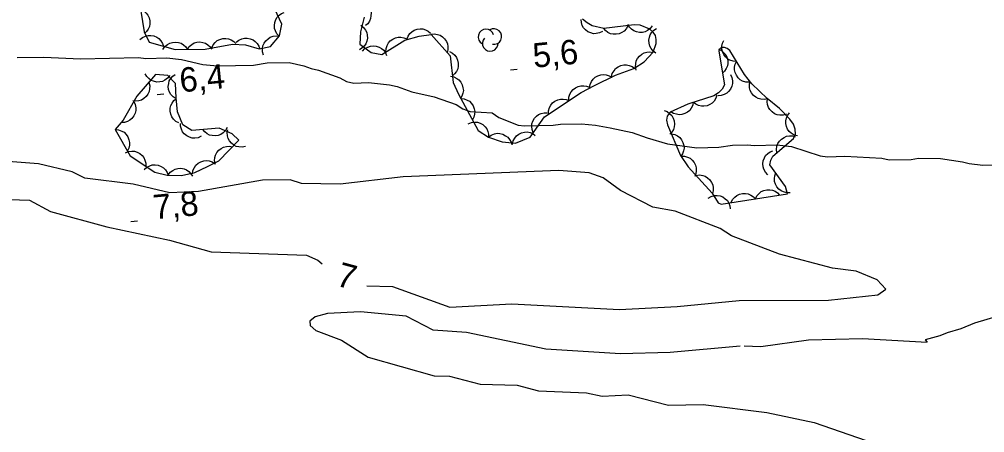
# Model space of a CAD drawing. Extents: x 336540 to 340074, y 5572036 to 5573747.
# Drawn here: x 336901.8 to 337020.3, y 5572687.6 to 5572738.3 of the extents above; entities that cross this region are included whole.
import ezdxf

# ---------------------------------------------------------------- set-up
doc = ezdxf.new("R2010")
doc.units = 0
for name, color, linetype in [('Niveau 2', 7, 'Continuous'), ('Niveau 3', 7, 'Continuous'), ('Niveau 44', 7, 'Continuous')]:
    doc.layers.add(name, color=color, linetype=linetype)

msp = doc.modelspace()

# ---------------------------------------------------------------- linework, layer by layer
at = {"layer": 'Niveau 2'}
for points in [[(336901.55, 5572733.62), (336904.82, 5572733.69), (336909.33, 5572733.46), (336916.43, 5572733.62), (336917.33, 5572733.53), (336919.92, 5572733.59), (336921.73, 5572733.4), (336924.34, 5572732.79), (336926.14, 5572732.6), (336930.54, 5572732.7), (336932.22, 5572732.97), (336934.93, 5572733.03), (336936.74, 5572732.62), (336937.65, 5572732.3), (336938.55, 5572732.1), (336941.17, 5572731.14), (336941.97, 5572730.71), (336942.87, 5572730.5), (336944.67, 5572730.55), (336947.27, 5572730.27), (336948.18, 5572730.06), (336950, 5572729.43), (336952.72, 5572728.81), (336955.44, 5572727.86), (336956.24, 5572727.32), (336957.15, 5572727), (336959.86, 5572726.83), (336960.66, 5572726.29), (336963.05, 5572725.33), (336963.84, 5572725.23), (336967.33, 5572725.31), (336968.23, 5572725.45), (336970.82, 5572725.51), (336972.52, 5572725.32), (336974.33, 5572725.02), (336977.05, 5572724.41), (336978.87, 5572723.77), (336981.36, 5572723.04)], [(336981.36, 5572723.04), (336984.08, 5572722.65), (336984.98, 5572722.56), (336987.68, 5572722.62), (336989.37, 5572722.89), (336991.17, 5572722.93), (336992.07, 5572722.84), (336994.78, 5572722.9), (336996.58, 5572722.71), (337000.11, 5572721.55), (337001.01, 5572721.46), (337003.15, 5572721.51), (337007.66, 5572721.28), (337008.57, 5572721.07), (337011.27, 5572721.13), (337012.17, 5572721.27), (337014.88, 5572721.22), (337017.59, 5572720.83), (337018.38, 5572720.62), (337020.08, 5572720.43), (337025.26, 5572720.55)], [(336944.47, 5572705.62), (336947.61, 5572705.51), (336954.67, 5572702.99), (336962.26, 5572703.38), (336975.49, 5572702.69), (336982.58, 5572703.05), (336990.15, 5572703.78), (337001.15, 5572703.84), (337007.2, 5572704.5), (337008.18, 5572705.21), (337007.1, 5572706.35), (337004.52, 5572707.41), (337001.62, 5572707.76), (336995.11, 5572709.47), (336989.24, 5572711.72), (336987.84, 5572712.65), (336982.32, 5572714.76), (336979.57, 5572715.27), (336975.59, 5572717.29), (336973.48, 5572718.87), (336971.75, 5572719.46), (336968.02, 5572719.77), (336948.94, 5572718.98), (336941.2, 5572718.07), (336936.46, 5572718.15), (336935.08, 5572718.61), (336931.68, 5572718.59), (336923.81, 5572717.17), (336920.28, 5572717), (336915.81, 5572718.1), (336909.86, 5572718.83), (336908.3, 5572719.58), (336904.18, 5572720.57), (336897.73, 5572721.07)], [(336899.33, 5572716.24), (336903.06, 5572716.11), (336905.65, 5572714.72), (336912.54, 5572712.86), (336920.24, 5572711.22), (336925.38, 5572709.78), (336937.08, 5572709.38), (336938.47, 5572708.76), (336938.98, 5572708.29)], [(336990.28, 5572698.2), (336981.69, 5572697.42), (336975.6, 5572697.27), (336966.44, 5572697.82), (336956.69, 5572699.85), (336952.6, 5572700.17), (336949.31, 5572701.88), (336943.68, 5572702.42), (336939.64, 5572702.22), (336938.14, 5572701.8), (336937.49, 5572701.26), (336937.51, 5572700.74), (336938.23, 5572700.12), (336941.35, 5572698.91), (336944.65, 5572696.86), (336952.73, 5572694.56), (336954.61, 5572694.5), (336958.36, 5572693.51), (336962.94, 5572693.4), (336965.53, 5572692.69), (336971.45, 5572692.46), (336973.34, 5572692.07), (336976.53, 5572692.23), (336981.51, 5572690.96), (336985.74, 5572691.01), (336993.58, 5572690.05), (336999.39, 5572688.81), (337005.75, 5572686.62)], [(337023.2, 5572702.25), (337019.05, 5572701.02)], [(337019.05, 5572701.02), (337017.38, 5572700.31), (337015.7, 5572699.82), (337014.81, 5572699.46), (337013.01, 5572698.97), (337013.25, 5572698.69)], [(336990.79, 5572698.23), (336992.81, 5572698.14), (336998.68, 5572698.98), (337005.29, 5572699.14), (337013.25, 5572698.69)]]:
    msp.add_lwpolyline(points, dxfattribs=at)
at = {"layer": 'Niveau 3'}
for p, q in [((336962.11, 5572732.13), (336962.91, 5572732.21)), ((336918.75, 5572729.11), (336919.55, 5572729.19)), ((336915.51, 5572713.52), (336916.31, 5572713.6))]:
    msp.add_line(p, q, dxfattribs=at)
at = {"layer": 'Niveau 44'}
for points in [[(336916.38, 5572741.65), (336917.14, 5572736.8), (336917.75, 5572735.52), (336920.94, 5572734.63), (336924.63, 5572734.66), (336927.99, 5572735.27), (336929.56, 5572735.19), (336931.25, 5572734.71), (336932.63, 5572734.97), (336933.74, 5572736.32), (336934.04, 5572737.75), (336932.63, 5572740.76)], [(336943.87, 5572740.51), (336944.25, 5572740.33), (336944.55, 5572740.06), (336944.76, 5572739.8), (336944.9, 5572739.48), (336944.99, 5572739.12), (336944.98, 5572738.74), (336944.94, 5572738.42), (336944.79, 5572738.1), (336944.58, 5572737.79), (336944.32, 5572737.55)], [(336916.71, 5572739.53), (336917.09, 5572739.36), (336917.39, 5572739.08), (336917.61, 5572738.83), (336917.75, 5572738.51), (336917.84, 5572738.15), (336917.83, 5572737.77), (336917.79, 5572737.44), (336917.65, 5572737.12), (336917.44, 5572736.82), (336917.18, 5572736.57)], [(336933.72, 5572736.24), (336933.43, 5572736.54), (336933.25, 5572736.9), (336933.14, 5572737.21), (336933.12, 5572737.56), (336933.16, 5572737.93), (336933.3, 5572738.29), (336933.45, 5572738.58), (336933.7, 5572738.82), (336934.01, 5572739.04), (336934.34, 5572739.17)], [(336943.72, 5572737.6), (336944.06, 5572737.34), (336944.29, 5572737.01), (336944.45, 5572736.72), (336944.52, 5572736.38), (336944.54, 5572736.01), (336944.45, 5572735.64), (336944.35, 5572735.33), (336944.14, 5572735.04), (336943.87, 5572734.79), (336943.56, 5572734.6)], [(336944.16, 5572738.6), (336943.68, 5572736.8), (336943.6, 5572735.28), (336944.99, 5572734.24), (336946.31, 5572734), (336949.12, 5572735.77), (336950.91, 5572736.26), (336952.35, 5572736.47), (336954.68, 5572733.85), (336955.08, 5572730.55), (336955.72, 5572729.12), (336958.15, 5572724.69), (336959.42, 5572723.85), (336961.09, 5572723.3), (336962.71, 5572723.13), (336964.52, 5572723.84), (336966.27, 5572726.37), (336970.79, 5572729.33), (336972.41, 5572730.21), (336975, 5572731.45), (336977.24, 5572732.3), (336978.51, 5572733.12), (336979.61, 5572734.3), (336979.98, 5572735.35), (336979.99, 5572735.86), (336979.91, 5572736.35), (336979.63, 5572736.75), (336979.2, 5572737.11), (336978.02, 5572737.6), (336977.3, 5572737.64), (336973.56, 5572737.22), (336972.14, 5572737.53), (336971.51, 5572737.88), (336970.94, 5572738.35)], [(336973.39, 5572736.83), (336973.02, 5572736.65), (336972.62, 5572736.58), (336972.29, 5572736.56), (336971.95, 5572736.65), (336971.61, 5572736.8), (336971.31, 5572737.04), (336971.08, 5572737.27), (336970.92, 5572737.58), (336970.8, 5572737.93), (336970.77, 5572738.29)], [(336979.51, 5572737.52), (336979.26, 5572737.18), (336978.93, 5572736.95), (336978.64, 5572736.79), (336978.29, 5572736.72), (336977.92, 5572736.71), (336977.55, 5572736.79), (336977.24, 5572736.9), (336976.96, 5572737.11), (336976.7, 5572737.37), (336976.52, 5572737.68)], [(336949.39, 5572735.84), (336949.53, 5572736.24), (336949.76, 5572736.57), (336949.99, 5572736.81), (336950.29, 5572736.99), (336950.64, 5572737.12), (336951.02, 5572737.15), (336951.35, 5572737.15), (336951.68, 5572737.04), (336952.01, 5572736.87), (336952.29, 5572736.64)], [(336952.33, 5572736.49), (336952.75, 5572736.55), (336953.15, 5572736.48), (336953.46, 5572736.38), (336953.76, 5572736.19), (336954.02, 5572735.94), (336954.23, 5572735.61), (336954.37, 5572735.32), (336954.42, 5572734.97), (336954.41, 5572734.6), (336954.32, 5572734.25)], [(336976.52, 5572737.55), (336976.33, 5572737.18), (336976.04, 5572736.89), (336975.78, 5572736.69), (336975.45, 5572736.56), (336975.09, 5572736.49), (336974.71, 5572736.51), (336974.38, 5572736.56), (336974.07, 5572736.72), (336973.77, 5572736.94), (336973.54, 5572737.22)], [(336979.96, 5572734.19), (336979.62, 5572734.43), (336979.37, 5572734.75), (336979.2, 5572735.04), (336979.12, 5572735.38), (336979.09, 5572735.75), (336979.16, 5572736.12), (336979.26, 5572736.44), (336979.46, 5572736.73), (336979.71, 5572736.99), (336980.02, 5572737.19)], [(336916.61, 5572735.84), (336916.93, 5572736.11), (336917.3, 5572736.27), (336917.62, 5572736.36), (336917.97, 5572736.36), (336918.33, 5572736.29), (336918.68, 5572736.12), (336918.96, 5572735.96), (336919.19, 5572735.69), (336919.38, 5572735.37), (336919.5, 5572735.03)], [(336919.44, 5572734.62), (336919.67, 5572734.97), (336919.99, 5572735.22), (336920.27, 5572735.4), (336920.61, 5572735.49), (336920.98, 5572735.53), (336921.35, 5572735.47), (336921.67, 5572735.38), (336921.96, 5572735.19), (336922.24, 5572734.94), (336922.44, 5572734.64)], [(336922.44, 5572734.64), (336922.67, 5572734.99), (336922.99, 5572735.25), (336923.27, 5572735.42), (336923.61, 5572735.52), (336923.98, 5572735.55), (336924.35, 5572735.49), (336924.67, 5572735.4), (336924.96, 5572735.21), (336925.24, 5572734.96), (336925.44, 5572734.67)], [(336925.43, 5572734.81), (336925.6, 5572735.19), (336925.86, 5572735.5), (336926.11, 5572735.72), (336926.43, 5572735.86), (336926.78, 5572735.96), (336927.17, 5572735.97), (336927.49, 5572735.94), (336927.82, 5572735.8), (336928.13, 5572735.6), (336928.38, 5572735.34)], [(336928.43, 5572735.51), (336928.75, 5572735.78), (336929.12, 5572735.94), (336929.44, 5572736.03), (336929.79, 5572736.02), (336930.16, 5572735.95), (336930.5, 5572735.79), (336930.78, 5572735.62), (336931.01, 5572735.35), (336931.2, 5572735.03), (336931.32, 5572734.69)], [(336931.78, 5572733.94), (336931.66, 5572734.34), (336931.67, 5572734.75), (336931.71, 5572735.07), (336931.86, 5572735.39), (336932.07, 5572735.7), (336932.36, 5572735.95), (336932.62, 5572736.14), (336932.96, 5572736.24), (336933.33, 5572736.29), (336933.69, 5572736.26)], [(336946.82, 5572734.32), (336946.83, 5572734.74), (336946.97, 5572735.12), (336947.11, 5572735.42), (336947.35, 5572735.68), (336947.65, 5572735.9), (336948, 5572736.05), (336948.31, 5572736.14), (336948.66, 5572736.13), (336949.03, 5572736.07), (336949.36, 5572735.92)], [(336989.84, 5572733.16), (336989.42, 5572733.18), (336989.04, 5572733.32), (336988.75, 5572733.47), (336988.49, 5572733.72), (336988.27, 5572734.01), (336988.13, 5572734.37), (336988.05, 5572734.68), (336988.06, 5572735.04), (336988.13, 5572735.4), (336988.28, 5572735.73)], [(336943.95, 5572734.43), (336944.24, 5572734.73), (336944.6, 5572734.92), (336944.91, 5572735.04), (336945.26, 5572735.07), (336945.63, 5572735.03), (336945.99, 5572734.9), (336946.28, 5572734.76), (336946.54, 5572734.52), (336946.76, 5572734.22), (336946.9, 5572733.89)], [(336954.62, 5572734.38), (336954.99, 5572734.19), (336955.28, 5572733.91), (336955.48, 5572733.65), (336955.61, 5572733.32), (336955.69, 5572732.96), (336955.67, 5572732.58), (336955.62, 5572732.25), (336955.47, 5572731.94), (336955.25, 5572731.64), (336954.98, 5572731.4)], [(336977.53, 5572732.07), (336977.44, 5572732.48), (336977.47, 5572732.88), (336977.53, 5572733.21), (336977.7, 5572733.52), (336977.93, 5572733.81), (336978.23, 5572734.04), (336978.51, 5572734.21), (336978.85, 5572734.29), (336979.22, 5572734.32), (336979.58, 5572734.27)], [(336996.12, 5572716.89), (336995.86, 5572717.81), (336993.94, 5572720.45), (336994.06, 5572721.03), (336994.32, 5572721.53), (336996.83, 5572723.71), (336997.07, 5572724.22), (336997.03, 5572724.82), (336996.82, 5572725.44), (336996.37, 5572726.08), (336995.1, 5572727.37), (336993.6, 5572728.61), (336991.73, 5572730.41), (336990.81, 5572731.56), (336989.04, 5572734.48), (336988.69, 5572734.75), (336988.38, 5572734.87), (336988.05, 5572734.85), (336987.79, 5572734.7), (336987.66, 5572734.41), (336988.37, 5572730.28), (336988.07, 5572729.75), (336987.64, 5572729.28), (336987.07, 5572728.92), (336983.87, 5572727.9), (336981.72, 5572726.93), (336981.33, 5572726.44), (336981.25, 5572725.93), (336981.39, 5572725.36), (336982.97, 5572721.62), (336983.91, 5572720.23), (336986.85, 5572716.96), (336987.61, 5572715.78), (336987.94, 5572715.62), (336996.12, 5572716.89)], [(336987.62, 5572734.67), (336988, 5572734.5), (336988.3, 5572734.23), (336988.52, 5572733.98), (336988.67, 5572733.66), (336988.76, 5572733.31), (336988.76, 5572732.92), (336988.73, 5572732.6), (336988.59, 5572732.27), (336988.38, 5572731.96), (336988.12, 5572731.71)], [(336991.39, 5572730.6), (336990.98, 5572730.62), (336990.59, 5572730.75), (336990.3, 5572730.91), (336990.05, 5572731.15), (336989.83, 5572731.45), (336989.69, 5572731.8), (336989.6, 5572732.12), (336989.61, 5572732.47), (336989.69, 5572732.83), (336989.84, 5572733.16)], [(336974.51, 5572731.26), (336974.6, 5572731.67), (336974.81, 5572732.02), (336975.01, 5572732.28), (336975.3, 5572732.49), (336975.63, 5572732.65), (336976.01, 5572732.72), (336976.33, 5572732.75), (336976.67, 5572732.67), (336977.02, 5572732.53), (336977.31, 5572732.33)], [(336913.59, 5572724.79), (336915.44, 5572721.55), (336918.46, 5572719.57), (336919.96, 5572719.21), (336921.71, 5572719.13), (336923.34, 5572719.5), (336924.93, 5572720.24), (336926.31, 5572720.97), (336928.75, 5572723.49), (336927.93, 5572724.26), (336926.33, 5572724.96), (336923, 5572724.67), (336921.9, 5572725.36), (336921.24, 5572726.97), (336921.05, 5572728.68), (336920.98, 5572730.44), (336920.03, 5572731.44), (336918.54, 5572731.54), (336916.23, 5572728.89), (336914.55, 5572725.96), (336913.59, 5572724.79)], [(336917.71, 5572730.59), (336917.82, 5572730.18), (336917.8, 5572729.78), (336917.75, 5572729.45), (336917.59, 5572729.14), (336917.37, 5572728.84), (336917.08, 5572728.6), (336916.8, 5572728.42), (336916.47, 5572728.32), (336916.1, 5572728.28), (336915.74, 5572728.33)], [(336920.27, 5572731.42), (336920.02, 5572731.09), (336919.68, 5572730.86), (336919.39, 5572730.71), (336919.05, 5572730.64), (336918.68, 5572730.63), (336918.3, 5572730.72), (336918, 5572730.83), (336917.72, 5572731.04), (336917.46, 5572731.31), (336917.28, 5572731.62)], [(336921.05, 5572728.58), (336920.7, 5572728.8), (336920.43, 5572729.1), (336920.25, 5572729.38), (336920.14, 5572729.71), (336920.1, 5572730.08), (336920.15, 5572730.46), (336920.22, 5572730.78), (336920.4, 5572731.08), (336920.65, 5572731.36), (336920.93, 5572731.57)], [(336954.73, 5572731.33), (336955.14, 5572731.26), (336955.5, 5572731.08), (336955.78, 5572730.89), (336956, 5572730.62), (336956.18, 5572730.29), (336956.27, 5572729.92), (336956.32, 5572729.6), (336956.26, 5572729.25), (336956.14, 5572728.9), (336955.95, 5572728.6)], [(336971.82, 5572729.93), (336971.88, 5572730.34), (336972.06, 5572730.71), (336972.24, 5572730.98), (336972.5, 5572731.21), (336972.82, 5572731.4), (336973.19, 5572731.51), (336973.51, 5572731.56), (336973.86, 5572731.51), (336974.21, 5572731.4), (336974.53, 5572731.22)], [(336989.09, 5572731.55), (336989.27, 5572731.17), (336989.34, 5572730.77), (336989.35, 5572730.44), (336989.26, 5572730.1), (336989.11, 5572729.77), (336988.87, 5572729.47), (336988.64, 5572729.24), (336988.32, 5572729.08), (336987.97, 5572728.96), (336987.61, 5572728.94)], [(336993.64, 5572728.57), (336993.23, 5572728.48), (336992.83, 5572728.52), (336992.51, 5572728.59), (336992.2, 5572728.76), (336991.91, 5572728.99), (336991.68, 5572729.3), (336991.52, 5572729.58), (336991.44, 5572729.92), (336991.42, 5572730.29), (336991.48, 5572730.65)], [(336969.27, 5572728.34), (336969.28, 5572728.76), (336969.4, 5572729.14), (336969.55, 5572729.44), (336969.78, 5572729.7), (336970.07, 5572729.93), (336970.42, 5572730.08), (336970.73, 5572730.18), (336971.09, 5572730.18), (336971.45, 5572730.12), (336971.78, 5572729.98)], [(336915.86, 5572728.24), (336916.04, 5572727.87), (336916.11, 5572727.47), (336916.12, 5572727.14), (336916.03, 5572726.8), (336915.87, 5572726.46), (336915.63, 5572726.16), (336915.39, 5572725.94), (336915.08, 5572725.78), (336914.73, 5572725.67), (336914.37, 5572725.64)], [(336921.39, 5572725.6), (336921.02, 5572725.79), (336920.73, 5572726.08), (336920.53, 5572726.34), (336920.4, 5572726.66), (336920.33, 5572727.03), (336920.35, 5572727.41), (336920.41, 5572727.73), (336920.57, 5572728.05), (336920.79, 5572728.34), (336921.06, 5572728.58)], [(336956, 5572728.62), (336956.41, 5572728.58), (336956.79, 5572728.42), (336957.08, 5572728.26), (336957.32, 5572728), (336957.52, 5572727.7), (336957.65, 5572727.33), (336957.72, 5572727.02), (336957.69, 5572726.67), (336957.6, 5572726.31), (336957.44, 5572725.99)], [(336966.76, 5572726.69), (336966.77, 5572727.11), (336966.9, 5572727.5), (336967.04, 5572727.8), (336967.27, 5572728.06), (336967.56, 5572728.29), (336967.91, 5572728.44), (336968.22, 5572728.54), (336968.58, 5572728.54), (336968.94, 5572728.48), (336969.27, 5572728.34)], [(336984.54, 5572728.2), (336984.47, 5572727.79), (336984.29, 5572727.43), (336984.1, 5572727.15), (336983.83, 5572726.93), (336983.5, 5572726.75), (336983.13, 5572726.65), (336982.81, 5572726.61), (336982.46, 5572726.66), (336982.11, 5572726.78), (336981.8, 5572726.97)], [(336987.43, 5572729.03), (336987.31, 5572728.63), (336987.09, 5572728.29), (336986.87, 5572728.04), (336986.57, 5572727.86), (336986.23, 5572727.71), (336985.85, 5572727.66), (336985.53, 5572727.65), (336985.19, 5572727.74), (336984.85, 5572727.9), (336984.57, 5572728.12)], [(336995.96, 5572726.66), (336995.56, 5572726.54), (336995.15, 5572726.55), (336994.82, 5572726.59), (336994.5, 5572726.74), (336994.2, 5572726.95), (336993.95, 5572727.24), (336993.76, 5572727.51), (336993.66, 5572727.85), (336993.61, 5572728.21), (336993.65, 5572728.57)], [(336980.96, 5572727.13), (336981.35, 5572726.99), (336981.67, 5572726.74), (336981.91, 5572726.51), (336982.07, 5572726.2), (336982.19, 5572725.85), (336982.22, 5572725.47), (336982.21, 5572725.14), (336982.09, 5572724.81), (336981.91, 5572724.48), (336981.67, 5572724.22)], [(336964.9, 5572724.39), (336964.75, 5572724.78), (336964.72, 5572725.18), (336964.74, 5572725.51), (336964.86, 5572725.84), (336965.04, 5572726.17), (336965.31, 5572726.44), (336965.56, 5572726.65), (336965.88, 5572726.78), (336966.25, 5572726.86), (336966.61, 5572726.86)], [(336997.31, 5572724), (336996.9, 5572724.11), (336996.56, 5572724.33), (336996.31, 5572724.54), (336996.11, 5572724.83), (336995.97, 5572725.17), (336995.9, 5572725.55), (336995.89, 5572725.88), (336995.98, 5572726.22), (336996.13, 5572726.55), (336996.35, 5572726.84)], [(336913.59, 5572724.79), (336914.01, 5572724.76), (336914.39, 5572724.61), (336914.67, 5572724.45), (336914.92, 5572724.2), (336915.13, 5572723.9), (336915.26, 5572723.54), (336915.34, 5572723.22), (336915.32, 5572722.87), (336915.24, 5572722.51), (336915.08, 5572722.18)], [(336924.14, 5572723.96), (336923.76, 5572723.79), (336923.35, 5572723.74), (336923.02, 5572723.74), (336922.69, 5572723.85), (336922.36, 5572724.01), (336922.07, 5572724.27), (336921.85, 5572724.51), (336921.71, 5572724.83), (336921.61, 5572725.19), (336921.6, 5572725.55)], [(336927.33, 5572725.05), (336927.13, 5572724.68), (336926.83, 5572724.4), (336926.57, 5572724.2), (336926.24, 5572724.08), (336925.87, 5572724.02), (336925.49, 5572724.05), (336925.17, 5572724.11), (336924.86, 5572724.28), (336924.57, 5572724.51), (336924.34, 5572724.79)], [(336929.57, 5572722.72), (336929.17, 5572722.62), (336928.76, 5572722.65), (336928.44, 5572722.72), (336928.13, 5572722.89), (336927.84, 5572723.12), (336927.61, 5572723.42), (336927.44, 5572723.7), (336927.36, 5572724.04), (336927.33, 5572724.41), (336927.39, 5572724.77)], [(336956.92, 5572725.51), (336957.3, 5572725.66), (336957.71, 5572725.7), (336958.04, 5572725.69), (336958.37, 5572725.58), (336958.7, 5572725.4), (336958.98, 5572725.14), (336959.19, 5572724.89), (336959.33, 5572724.57), (336959.42, 5572724.21), (336959.42, 5572723.85)], [(336959.42, 5572723.85), (336959.75, 5572724.11), (336960.13, 5572724.25), (336960.45, 5572724.33), (336960.8, 5572724.3), (336961.16, 5572724.22), (336961.5, 5572724.04), (336961.77, 5572723.86), (336961.99, 5572723.58), (336962.17, 5572723.26), (336962.27, 5572722.91)], [(336962.35, 5572722.99), (336962.44, 5572723.4), (336962.64, 5572723.75), (336962.84, 5572724.01), (336963.12, 5572724.22), (336963.46, 5572724.38), (336963.83, 5572724.46), (336964.16, 5572724.5), (336964.5, 5572724.42), (336964.84, 5572724.29), (336965.14, 5572724.08)], [(336981.85, 5572724.28), (336982.26, 5572724.19), (336982.62, 5572724), (336982.88, 5572723.81), (336983.1, 5572723.53), (336983.27, 5572723.21), (336983.36, 5572722.83), (336983.4, 5572722.51), (336983.34, 5572722.16), (336983.21, 5572721.81), (336983.02, 5572721.51)], [(336994.79, 5572721.94), (336994.74, 5572722.35), (336994.81, 5572722.75), (336994.91, 5572723.07), (336995.11, 5572723.36), (336995.37, 5572723.63), (336995.69, 5572723.82), (336995.99, 5572723.96), (336996.34, 5572724.01), (336996.71, 5572724), (336997.06, 5572723.91)], [(336914.83, 5572721.95), (336915.21, 5572722.11), (336915.62, 5572722.15), (336915.95, 5572722.14), (336916.28, 5572722.03), (336916.61, 5572721.86), (336916.89, 5572721.59), (336917.1, 5572721.35), (336917.24, 5572721.03), (336917.33, 5572720.67), (336917.34, 5572720.31)], [(336925.88, 5572720.52), (336925.79, 5572720.93), (336925.83, 5572721.34), (336925.9, 5572721.66), (336926.07, 5572721.97), (336926.3, 5572722.25), (336926.61, 5572722.48), (336926.89, 5572722.64), (336927.24, 5572722.72), (336927.61, 5572722.74), (336927.96, 5572722.68)], [(336993.69, 5572719.25), (336993.4, 5572719.55), (336993.21, 5572719.92), (336993.1, 5572720.23), (336993.08, 5572720.58), (336993.13, 5572720.94), (336993.27, 5572721.3), (336993.42, 5572721.59), (336993.67, 5572721.84), (336993.97, 5572722.06), (336994.3, 5572722.19)], [(336923.06, 5572719.37), (336923.13, 5572719.78), (336923.31, 5572720.15), (336923.49, 5572720.42), (336923.76, 5572720.65), (336924.08, 5572720.83), (336924.45, 5572720.93), (336924.77, 5572720.99), (336925.12, 5572720.93), (336925.47, 5572720.82), (336925.78, 5572720.64)], [(336983.04, 5572721.52), (336983.45, 5572721.52), (336983.84, 5572721.4), (336984.14, 5572721.27), (336984.41, 5572721.04), (336984.64, 5572720.75), (336984.8, 5572720.4), (336984.9, 5572720.09), (336984.91, 5572719.74), (336984.85, 5572719.37), (336984.72, 5572719.04)], [(336917.15, 5572719.88), (336917.46, 5572720.17), (336917.83, 5572720.34), (336918.14, 5572720.44), (336918.5, 5572720.45), (336918.86, 5572720.4), (336919.21, 5572720.24), (336919.5, 5572720.09), (336919.74, 5572719.83), (336919.95, 5572719.52), (336920.07, 5572719.18)], [(336920.08, 5572719.2), (336920.32, 5572719.54), (336920.65, 5572719.78), (336920.94, 5572719.94), (336921.29, 5572720.01), (336921.65, 5572720.03), (336922.03, 5572719.95), (336922.34, 5572719.85), (336922.62, 5572719.64), (336922.88, 5572719.37), (336923.07, 5572719.07)], [(336984.87, 5572719.16), (336985.29, 5572719.22), (336985.69, 5572719.15), (336986, 5572719.06), (336986.3, 5572718.87), (336986.57, 5572718.61), (336986.77, 5572718.29), (336986.92, 5572718), (336986.97, 5572717.65), (336986.96, 5572717.28), (336986.88, 5572716.93)], [(336996.42, 5572717.04), (336996, 5572717.02), (336995.61, 5572717.13), (336995.31, 5572717.25), (336995.03, 5572717.48), (336994.79, 5572717.76), (336994.62, 5572718.1), (336994.51, 5572718.4), (336994.49, 5572718.76), (336994.54, 5572719.12), (336994.66, 5572719.46)], [(336986.38, 5572716.37), (336986.75, 5572716.58), (336987.14, 5572716.68), (336987.47, 5572716.71), (336987.82, 5572716.64), (336988.16, 5572716.51), (336988.47, 5572716.29), (336988.72, 5572716.07), (336988.9, 5572715.77), (336989.03, 5572715.42), (336989.08, 5572715.07)], [(336989.2, 5572715.82), (336989.37, 5572716.19), (336989.65, 5572716.49), (336989.9, 5572716.71), (336990.22, 5572716.85), (336990.58, 5572716.94), (336990.96, 5572716.93), (336991.29, 5572716.89), (336991.61, 5572716.75), (336991.92, 5572716.54), (336992.16, 5572716.28)], [(336992.16, 5572716.28), (336992.34, 5572716.65), (336992.61, 5572716.95), (336992.86, 5572717.17), (336993.19, 5572717.31), (336993.55, 5572717.4), (336993.93, 5572717.39), (336994.25, 5572717.35), (336994.57, 5572717.21), (336994.88, 5572717), (336995.13, 5572716.74)]]:
    msp.add_lwpolyline(points, dxfattribs=at)
for centre, start, end in [((336959.1, 5572736.17), 14.7722, 242.2293), ((336960.06, 5572736.21), 259.4399, 122.1242), ((336959.62, 5572735.37), 136.6184, 2.307)]:
    msp.add_arc(centre, 0.958, start, end, dxfattribs=at)

# ---------------------------------------------------------------- texts
at = {"layer": 'Niveau 2'}
msp.add_text('7', height=3, rotation=344.8642, dxfattribs=at).set_placement((336940.56, 5572705.66))
at = {"layer": 'Niveau 3'}
for s, p in [('5,6    ', (336964.98, 5572732.37)), ('6,4    ', (336921.62, 5572729.35)), ('7,8    ', (336918.38, 5572713.76))]:
    msp.add_text(s, height=3, rotation=5.5424, dxfattribs=at).set_placement(p)

doc.saveas('drawing.dxf')
